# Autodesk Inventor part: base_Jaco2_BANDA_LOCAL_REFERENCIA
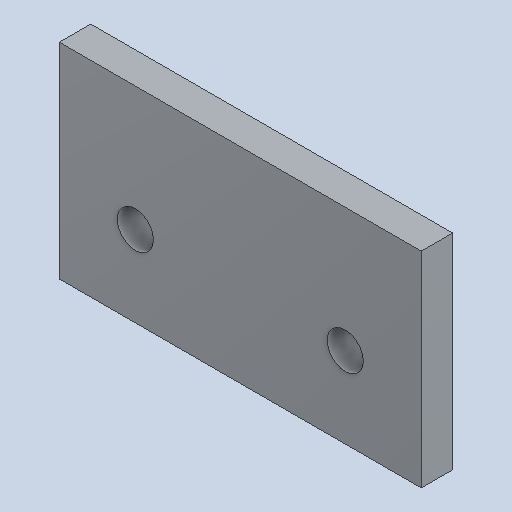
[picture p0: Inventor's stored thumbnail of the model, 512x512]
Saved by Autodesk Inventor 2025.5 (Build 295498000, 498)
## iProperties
Created: 2026-10
Part Number: base_Jaco2_BANDA_LOCAL_REFERENCIA
Material: Genérico
Document SubType Name: Modeling
Designer: Luis M
Density: 1 g/cm^3
Appearance: Valor por defecto
Author: Luis M
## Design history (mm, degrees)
feature "Base1"
node "Sólido1"
